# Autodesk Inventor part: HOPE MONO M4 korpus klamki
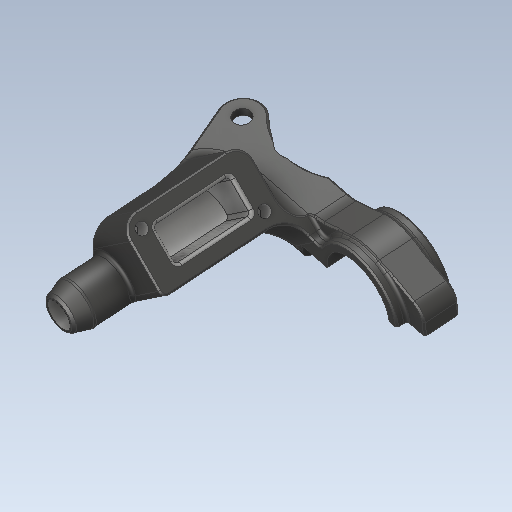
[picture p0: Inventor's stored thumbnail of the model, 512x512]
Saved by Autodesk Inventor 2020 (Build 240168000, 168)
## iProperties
Created: 2015-11
Part Number: HOPE MONO M4 korpus klamki
Material: Ogólny
Document SubType Name: Modeling
Designer: Tomasz
Density: 1 g/cm^3
Appearance: Domyślna
Sending System: SolidWorks 2017
Last Author: Tomasz
Last Saved: 2017-11-19
Author: Tomasz
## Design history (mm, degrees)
feature "Imported1"
node "Bryła1"
